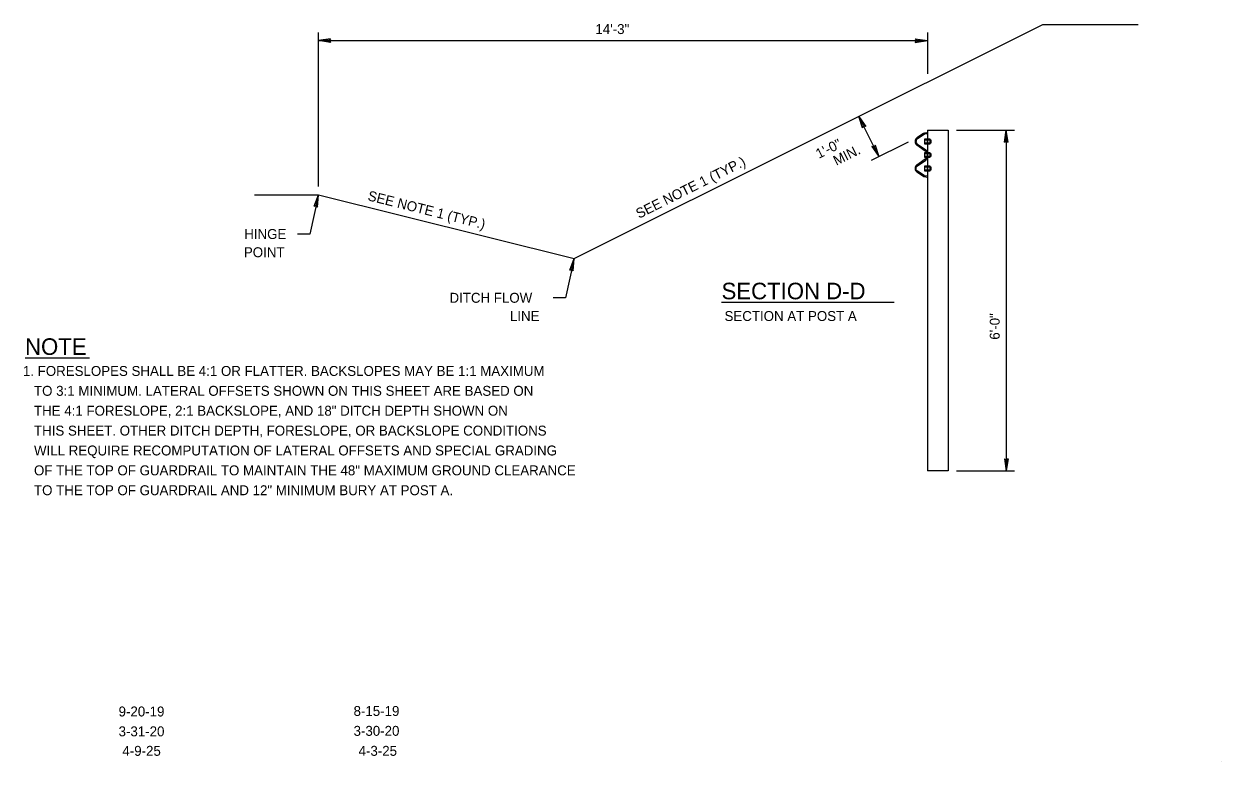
# Model space of a CAD drawing. Extents: x 12.4 to 19.6, y 6 to 16.
# Drawn here: x 12.4 to 19.62, y 5.98 to 10.43 of the extents above; entities that cross this region are included whole.
import ezdxf

# ---------------------------------------------------------------- set-up
doc = ezdxf.new("R2010")
doc.units = 0
for name, color, linetype in [('DETL-DIMS', 7, 'Continuous'), ('DETL-LINE', 7, 'Continuous'), ('DETL-NOTE', 7, 'Continuous'), ('DETL-TITL', 7, 'Continuous'), ('TTLB-TEXT', 7, 'Continuous')]:
    doc.layers.add(name, color=color, linetype=linetype)

msp = doc.modelspace()

# ---------------------------------------------------------------- linework, layer by layer
at = {"layer": 'DETL-DIMS'}
for p, q in [((14.1733, 9.4519), (14.1733, 10.3827)), ((14.2461, 10.3433), (14.1733, 10.3327)), ((14.1733, 10.3327), (17.8483, 10.3327)), ((14.2461, 10.3221), (14.1733, 10.3327)), ((14.2461, 10.3433), (14.237, 10.3327)), ((14.2461, 10.3221), (14.237, 10.3327)), ((17.7754, 10.3433), (17.8483, 10.3327)), ((17.7754, 10.3433), (17.7845, 10.3327)), ((17.7754, 10.3221), (17.8483, 10.3327)), ((17.7754, 10.3221), (17.7845, 10.3327)), ((17.8483, 10.3827), (17.8483, 10.1327)), ((17.556, 9.6328), (17.4345, 9.8758)), ((17.4766, 9.8153), (17.4345, 9.8758)), ((17.4576, 9.8058), (17.4345, 9.8758)), ((17.4576, 9.8058), (17.463, 9.8187)), ((17.4766, 9.8153), (17.463, 9.8187)), ((18.0241, 9.7927), (18.3748, 9.7927)), ((18.3142, 9.7199), (18.3248, 9.7927)), ((18.3248, 9.7927), (18.3248, 7.7352)), ((18.3354, 9.7199), (18.3248, 9.7927)), ((17.5112, 9.6104), (17.7349, 9.7222)), ((17.5139, 9.6932), (17.556, 9.6328)), ((17.5139, 9.6932), (17.5274, 9.6899)), ((17.5329, 9.7027), (17.5274, 9.6899)), ((17.5329, 9.7027), (17.556, 9.6328)), ((18.3142, 9.7199), (18.3248, 9.729)), ((18.3354, 9.7199), (18.3248, 9.729)), ((14.1733, 9.4019), (14.1217, 9.1656)), ((14.1474, 9.3329), (14.1733, 9.4019)), ((14.1681, 9.3284), (14.1733, 9.4019)), ((14.1474, 9.3329), (14.1597, 9.3395)), ((14.1681, 9.3284), (14.1597, 9.3395)), ((14.1217, 9.1656), (14.0467, 9.1656)), ((15.7166, 9.0169), (15.665, 8.7806)), ((15.6907, 8.9479), (15.7166, 9.0169)), ((15.7114, 8.9434), (15.7166, 9.0169)), ((15.6907, 8.9479), (15.703, 8.9545)), ((15.7114, 8.9434), (15.703, 8.9545)), ((15.665, 8.7806), (15.59, 8.7806)), ((18.3142, 7.808), (18.3248, 7.7352)), ((18.3142, 7.808), (18.3248, 7.7989)), ((18.3354, 7.808), (18.3248, 7.7352)), ((18.3354, 7.808), (18.3248, 7.7989)), ((18.0241, 7.7352), (18.3748, 7.7352))]:
    msp.add_line(p, q, dxfattribs=at)
for points in [[(14.2461, 10.3221), (14.1733, 10.3327), (14.2461, 10.3433), (14.237, 10.3327)], [(17.7754, 10.3433), (17.8483, 10.3327), (17.7754, 10.3221), (17.7845, 10.3327)], [(17.4576, 9.8058), (17.4345, 9.8758), (17.4766, 9.8153), (17.463, 9.8187)], [(18.3354, 9.7199), (18.3248, 9.7927), (18.3142, 9.7199), (18.3248, 9.729)], [(17.5139, 9.6932), (17.556, 9.6328), (17.5329, 9.7027), (17.5274, 9.6899)], [(14.1681, 9.3284), (14.1733, 9.4019), (14.1474, 9.3329), (14.1597, 9.3395)], [(15.7114, 8.9434), (15.7166, 9.0169), (15.6907, 8.9479), (15.703, 8.9545)], [(18.3142, 7.808), (18.3248, 7.7352), (18.3354, 7.808), (18.3248, 7.7989)]]:
    msp.add_lwpolyline(points, close=True, dxfattribs=at)
at = {"layer": 'DETL-LINE'}
for p, q in [((17.8483, 9.7927), (17.9741, 9.7927)), ((17.8483, 9.7927), (17.8483, 7.736)), ((17.9741, 9.7927), (17.9741, 7.736)), ((17.8328, 9.7398), (17.8483, 9.7398)), ((17.8328, 9.7089), (17.8328, 9.7398)), ((17.8483, 9.732), (17.8328, 9.732)), ((17.8328, 9.7166), (17.8483, 9.7166)), ((17.8483, 9.7089), (17.8328, 9.7089)), ((17.8483, 9.7398), (17.8483, 9.7089)), ((17.8483, 9.7398), (17.8638, 9.7398)), ((17.8483, 9.7089), (17.8483, 9.7398)), ((17.8638, 9.7321), (17.8483, 9.7321)), ((17.8483, 9.7167), (17.8638, 9.7167)), ((17.8638, 9.7089), (17.8483, 9.7089)), ((17.8638, 9.7398), (17.8638, 9.7089)), ((17.8715, 9.7321), (17.8638, 9.7321)), ((17.8638, 9.7167), (17.8715, 9.7167)), ((17.8715, 9.7167), (17.8715, 9.7321)), ((17.8328, 9.6581), (17.8483, 9.6581)), ((17.8328, 9.6273), (17.8328, 9.6581)), ((17.8483, 9.6504), (17.8328, 9.6504)), ((17.8328, 9.635), (17.8483, 9.635)), ((17.8483, 9.6273), (17.8328, 9.6273)), ((17.8483, 9.6581), (17.8483, 9.6273)), ((17.8483, 9.6581), (17.8638, 9.6581)), ((17.8483, 9.6273), (17.8483, 9.6581)), ((17.8638, 9.6504), (17.8483, 9.6504)), ((17.8483, 9.635), (17.8638, 9.635)), ((17.8638, 9.6273), (17.8483, 9.6273)), ((17.8638, 9.6581), (17.8638, 9.6273)), ((17.8715, 9.6504), (17.8638, 9.6504)), ((17.8638, 9.635), (17.8715, 9.635)), ((17.8715, 9.635), (17.8715, 9.6504)), ((17.8328, 9.5764), (17.8483, 9.5764)), ((17.8328, 9.5456), (17.8328, 9.5764)), ((17.8483, 9.5687), (17.8328, 9.5687)), ((17.8328, 9.5533), (17.8483, 9.5533)), ((17.8483, 9.5456), (17.8328, 9.5456)), ((17.8483, 9.5764), (17.8483, 9.5456)), ((17.8483, 9.5764), (17.8638, 9.5764)), ((17.8483, 9.5456), (17.8483, 9.5764)), ((17.8638, 9.5688), (17.8483, 9.5688)), ((17.8483, 9.5534), (17.8638, 9.5534)), ((17.8638, 9.5456), (17.8483, 9.5456)), ((17.8638, 9.5764), (17.8638, 9.5456)), ((17.8715, 9.5688), (17.8638, 9.5688)), ((17.8638, 9.5534), (17.8715, 9.5534)), ((17.8715, 9.5534), (17.8715, 9.5688)), ((17.9741, 7.736), (17.8483, 7.736))]:
    msp.add_line(p, q, dxfattribs=at)
for points in [[(13.7879, 9.4019), (14.1733, 9.4019), (15.7166, 9.0169), (18.545, 10.431), (19.1208, 10.431)], [(17.8458, 9.776), (17.83, 9.7735), (17.8275, 9.7727), (17.8258, 9.7727), (17.825, 9.7719), (17.785, 9.7452), (17.7825, 9.7427), (17.7791, 9.7402), (17.7766, 9.736), (17.775, 9.7327)], [(17.8483, 9.771), (17.8316, 9.7685), (17.83, 9.7677), (17.8291, 9.7677), (17.8283, 9.7669), (17.7891, 9.741), (17.7858, 9.7385), (17.7833, 9.736), (17.7816, 9.7319), (17.7808, 9.7285)], [(17.8483, 9.7769), (17.8458, 9.776)], [(17.775, 9.7327), (17.7741, 9.7285), (17.7741, 9.7202), (17.775, 9.716)], [(17.775, 9.716), (17.7766, 9.7127), (17.7816, 9.706), (17.785, 9.7035), (17.835, 9.6685), (17.8366, 9.6677), (17.8383, 9.6652), (17.84, 9.6635), (17.8436, 9.6581)], [(17.7858, 9.7102), (17.7883, 9.7077), (17.8383, 9.6735), (17.845, 9.6669), (17.8466, 9.6635), (17.8483, 9.6594), (17.8483, 9.6552), (17.8483, 9.6494), (17.8483, 9.636), (17.8483, 9.6377)], [(17.8375, 9.6185), (17.835, 9.6169), (17.785, 9.5819), (17.7816, 9.5794), (17.7766, 9.5727), (17.775, 9.5694)], [(17.8483, 9.5144), (17.8316, 9.5169), (17.83, 9.5177), (17.8291, 9.5177), (17.8283, 9.5185), (17.7891, 9.5444), (17.7858, 9.5469), (17.7833, 9.5494), (17.7816, 9.5535), (17.7808, 9.5569), (17.78, 9.561), (17.78, 9.5644), (17.7816, 9.5685), (17.7833, 9.5719), (17.7858, 9.5752), (17.7883, 9.5777), (17.8383, 9.6119), (17.845, 9.6185), (17.8466, 9.6219), (17.8483, 9.626), (17.8483, 9.631), (17.8483, 9.636)], [(17.775, 9.5694), (17.7741, 9.5652), (17.7741, 9.5569), (17.775, 9.5527)], [(17.775, 9.5527), (17.7766, 9.5494), (17.7791, 9.546), (17.785, 9.5402), (17.825, 9.5144), (17.8258, 9.5127), (17.8275, 9.5127), (17.83, 9.5119), (17.8458, 9.5094)], [(17.8458, 9.5094), (17.8483, 9.5085)]]:
    msp.add_lwpolyline(points, dxfattribs=at)
for points in [[(17.7808, 9.7285), (17.7781, 9.7214), (17.7815, 9.7157), (17.7858, 9.7102)], [(17.8375, 9.6185), (17.84, 9.6218), (17.8414, 9.6245), (17.8421, 9.6273)]]:
    msp.add_open_spline(points, degree=2, dxfattribs=at)
at = {"layer": 'DETL-NOTE'}
msp.add_line((12.4023, 8.419), (12.7908, 8.419), dxfattribs=at)
at = {"layer": 'DETL-TITL'}
msp.add_line((16.606, 8.7533), (17.6483, 8.7533), dxfattribs=at)
at = {"layer": 'TTLB-TEXT'}
msp.add_line((19.6208, 5.9844), (19.6208, 5.9844), dxfattribs=at)

# ---------------------------------------------------------------- texts
at = {"layer": 'DETL-NOTE'}
for s, height, rotation, p in [('14\'-3"', 0.06, 360, (15.8447, 10.3727)), ('1\'-0"', 0.06, 26.56505, (17.1933, 9.6186)), ('MIN.', 0.06, 26.56505, (17.2988, 9.5774)), ('SEE NOTE 1 (TYP.)', 0.06, 26.56505, (16.1078, 9.2572)), ('SEE NOTE 1 (TYP.)', 0.06, 345.99288, (14.4667, 9.3699)), ('HINGE', 0.06, 360, (13.7254, 9.1356)), ('POINT', 0.06, 360, (13.7233, 9.0256)), ('DITCH FLOW', 0.06, 360, (14.9642, 8.7506)), ('LINE', 0.06, 360, (15.3287, 8.6406)), ('SECTION AT POST A', 0.06, 360, (16.6241, 8.6406)), ('6\'-0"', 0.06, 90, (18.2848, 8.5278)), ('NOTE', 0.1, 360, (12.4023, 8.4361))]:
    msp.add_text(s, height=height, rotation=rotation, dxfattribs=at).set_placement(p)
for s, p in [('1. FORESLOPES SHALL BE 4:1 OR FLATTER. BACKSLOPES MAY BE 1:1 MAXIMUM', (12.3896, 8.309)), ('   TO 3:1 MINIMUM. LATERAL OFFSETS SHOWN ON THIS SHEET ARE BASED ON', (12.3896, 8.189)), ('   THE 4:1 FORESLOPE, 2:1 BACKSLOPE, AND 18" DITCH DEPTH SHOWN ON', (12.3896, 8.069)), ('   THIS SHEET. OTHER DITCH DEPTH, FORESLOPE, OR BACKSLOPE CONDITIONS', (12.3896, 7.949)), ('   WILL REQUIRE RECOMPUTATION OF LATERAL OFFSETS AND SPECIAL GRADING', (12.3896, 7.829)), ('   OF THE TOP OF GUARDRAIL TO MAINTAIN THE 48" MAXIMUM GROUND CLEARANCE', (12.3896, 7.709)), ('   TO THE TOP OF GUARDRAIL AND 12" MINIMUM BURY AT POST A.', (12.3896, 7.589))]:
    msp.add_text(s, height=0.06, dxfattribs=at).set_placement(p)
at = {"layer": 'DETL-TITL'}
msp.add_text('SECTION D-D', height=0.1, rotation=360, dxfattribs=at).set_placement((16.606, 8.7716))
at = {"layer": 'TTLB-TEXT'}
for s, p in [('9-20-19', (12.9671, 6.2537)), ('8-15-19', (14.3853, 6.2567)), ('3-31-20', (12.9671, 6.1337)), ('3-30-20', (14.3853, 6.1367))]:
    msp.add_text(s, height=0.06, rotation=360, dxfattribs=at).set_placement(p)
for s, p in [('4-9-25', (12.99, 6.0161)), ('4-3-25', (14.4155, 6.0161))]:
    msp.add_text(s, height=0.06, dxfattribs=at).set_placement(p)

doc.saveas('drawing.dxf')
